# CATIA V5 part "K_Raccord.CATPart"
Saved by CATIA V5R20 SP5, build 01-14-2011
Part number: Raccord
Bounding box of the stored display mesh (mm): x -25 to 25, y -70 to 70, z -25 to 27
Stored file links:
  G:\Khaled_CFAO_2011\ST2M\ST2M_GR2\amorin\Khaled\CAD_Modification\K_Raccord.CATPart
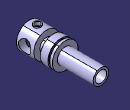
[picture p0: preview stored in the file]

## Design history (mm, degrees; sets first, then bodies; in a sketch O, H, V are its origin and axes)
Body1 (main body)
  Sketch1 on yz-plane, origin (0, 0, 0), H (0, 1, 0), V (0, 0, 1)
    point P1 (0, 25)
    point P2 (-70, 25)
    line L1 (0, 25) -> (0, 15)
    line L2 (0, 15) -> (70, 15)
    line L3 (70, 0) -> (70, 15)
    point P5 (70, 0)
    line L4 (-70, 25) -> (-70, 0)
    point P6 (-70, 0)
    line L5 (-5, 25) -> (-5, 22)
    line L6 (-5, 22) -> (-8.4187, 22)
    line L7 (-8.4187, 22) -> (-8.4187, 25)
    line L8 (-5, 25) -> (0, 25)
    line L9 (-23.306, 25) -> (-23.306, 13)
    line L10 (-23.306, 13) -> (-36.306, 13)
    line L11 (-36.306, 13) -> (-36.306, 25)
    line L12 (-23.306, 25) -> (-8.4187, 25)
    line L13 (-36.306, 25) -> (-70, 25)
    length L3 = 15
    length L4 = 25
    length L2 = 70
    distance P2 P1 = 70
    coincidence: P1 V, P5 H, P6 H
    vertical: L1 V, L3 V, L4 V, L5 V, L7 V, L9 V, L11 V
    horizontal: L2 H, L6 H, L8 H, L10 H, L12 H, L13 H
  Shaft1: profile Sketch1, axis Sketch1.H, angle 360
  Sketch2 on face of Shaft1 from Sketch1.L4, origin (0, -70, 0), H (1, 0, 0), V (0, 0, 1)
    point P1 (0, 0)
  Hole1: placed by Sketch2, at (0, -70, 0) direction (0, 1, 0), diameter 22, through (limit type 3)
  Sketch3 on face of Shaft1 from Sketch1.L4, origin (0, -70, 0), H (1, 0, 0), V (0, 0, 1)
    point P1 (-11, 0)
    line L1 (-11, 0) -> (11, 0)
    line L2 (11, 0) -> (11, -20)
    line L3 (11, -20) -> (-11, -20)
    line L4 (-11, -20) -> (-11, 0)
    coincidence: P1 H
    horizontal: L1 H, L3 H
    vertical: L2 V, L4 V
  Pocket1: profile Sketch3, direction (0, 1, 0), length 20
  Sketch4 on yz-plane, origin (0, 0, 0), H (0, 1, 0), V (0, 0, 1)
    line L1 (-50, 0) -> (-70, -20)
    point P1 (-50, 0)
    point P2 (-70, -20)
    line L2 (-70, -20) -> (-50, -20)
    point P3 (-70, -20)
    line L3 (-50, 0) -> (-50, -20)
    point P5 (-50, 0)
    coincidence: P1 H, P3 L1, P5 L1, P5 H, P1 P5, P2 P3
    horizontal: L2 H
    vertical: L3 V
  Pad1: profile Sketch4, direction (1, 0, 0), length 12, mirrored extent
  Sketch5 on yz-plane, origin (0, 0, 0), H (0, 1, 0), V (0, 0, 1)
    circle A1 centre (-54, 0) radius 12
    point P1 (-54, 0)
    point P2 (-42, 0)
    coincidence: P1 H, A1 P2, P2 H
  Pad2: profile Sketch5, direction (1, 0, 0), length 27, mirrored extent
  Sketch6 on end face of Pad2, origin (27, -54, 0), H (0, 1, 0), V (0, 0, 1)
    point P1 (0, 0)
  Hole2: placed by Sketch6, at (27, -54, 0) direction (-1, 0, 0), diameter 24, through (limit type 3)
  Fillet1: radius 1, on edge [face of Pocket1 from Sketch3.L2 | face of Pad1 from Sketch4.L1]; edge [face of Pocket1 from Sketch3.L4 | face of Pad1 from Sketch4.L1]
  Fillet2: radius 1, on edge [face of Shaft1 from Sketch1.L6 | face of Shaft1 from Sketch1.L5]
  Fillet3: radius 1, on edge [face of Shaft1 from Sketch1.L7 | face of Shaft1 from Sketch1.L6]
  Sketch7 on xy-plane, origin (0, 0, 0), H (1, 0, 0), V (0, 1, 0)
    circle A1 centre (0, -54) radius 5
    point P1 (0, -54)
    reference projected line E1 through (0, -54) direction (-1, 0) from axis of face of Hole2
    distance P1 E1 = 0
    coincidence: P1 V
  Pad3: profile Sketch7, direction (0, 0, 1), length 27
  Sketch8 on end face of Pad3, origin (0, 0, 27), H (1, 0, 0), V (0, 1, 0)
    circle A1 centre (0, -53.9645) radius 7
    point P1 (0, -53.9645)
    coincidence: P1 V
  Pad4: profile Sketch8, direction (0, 0, -1), length 10
  Sketch9 on face of Pad4, origin (0, -54, 27), H (1, 0, 0), V (0, 1, 0)
    point P1 (0, 0)
  Hole3: placed by Sketch9, at (0, -54, 27) direction (0, 0, -1), diameter 10, through (limit type 6), threaded, thread diameter 11, thread depth 9, pitch 1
